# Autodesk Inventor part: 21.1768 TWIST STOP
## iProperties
Created: 2007-03
Part Number: 21.1768 TWIST STOP
Document SubType Name: Modeling
Designer: Andy Moles
Material: Steel
Mass: 32.5786 g
Surface Area: 37.3237 cm^2
Volume: 4.15013 cm^3
Density: 7.85 g/cm^3
Author: Andy Moles
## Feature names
1. Extrusion1
2. Extrusion2
3. Extrusion3
4. Extrusion4
5. Hole1
6. Hole2
7. Extrusion5
